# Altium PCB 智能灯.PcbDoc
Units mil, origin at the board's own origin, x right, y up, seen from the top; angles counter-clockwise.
Board outline 3947.04 x 3947.04 mil, 2 copper layers (Top Layer, Bottom Layer); 72 components, 44 nets, 338 pads, 4 vias.
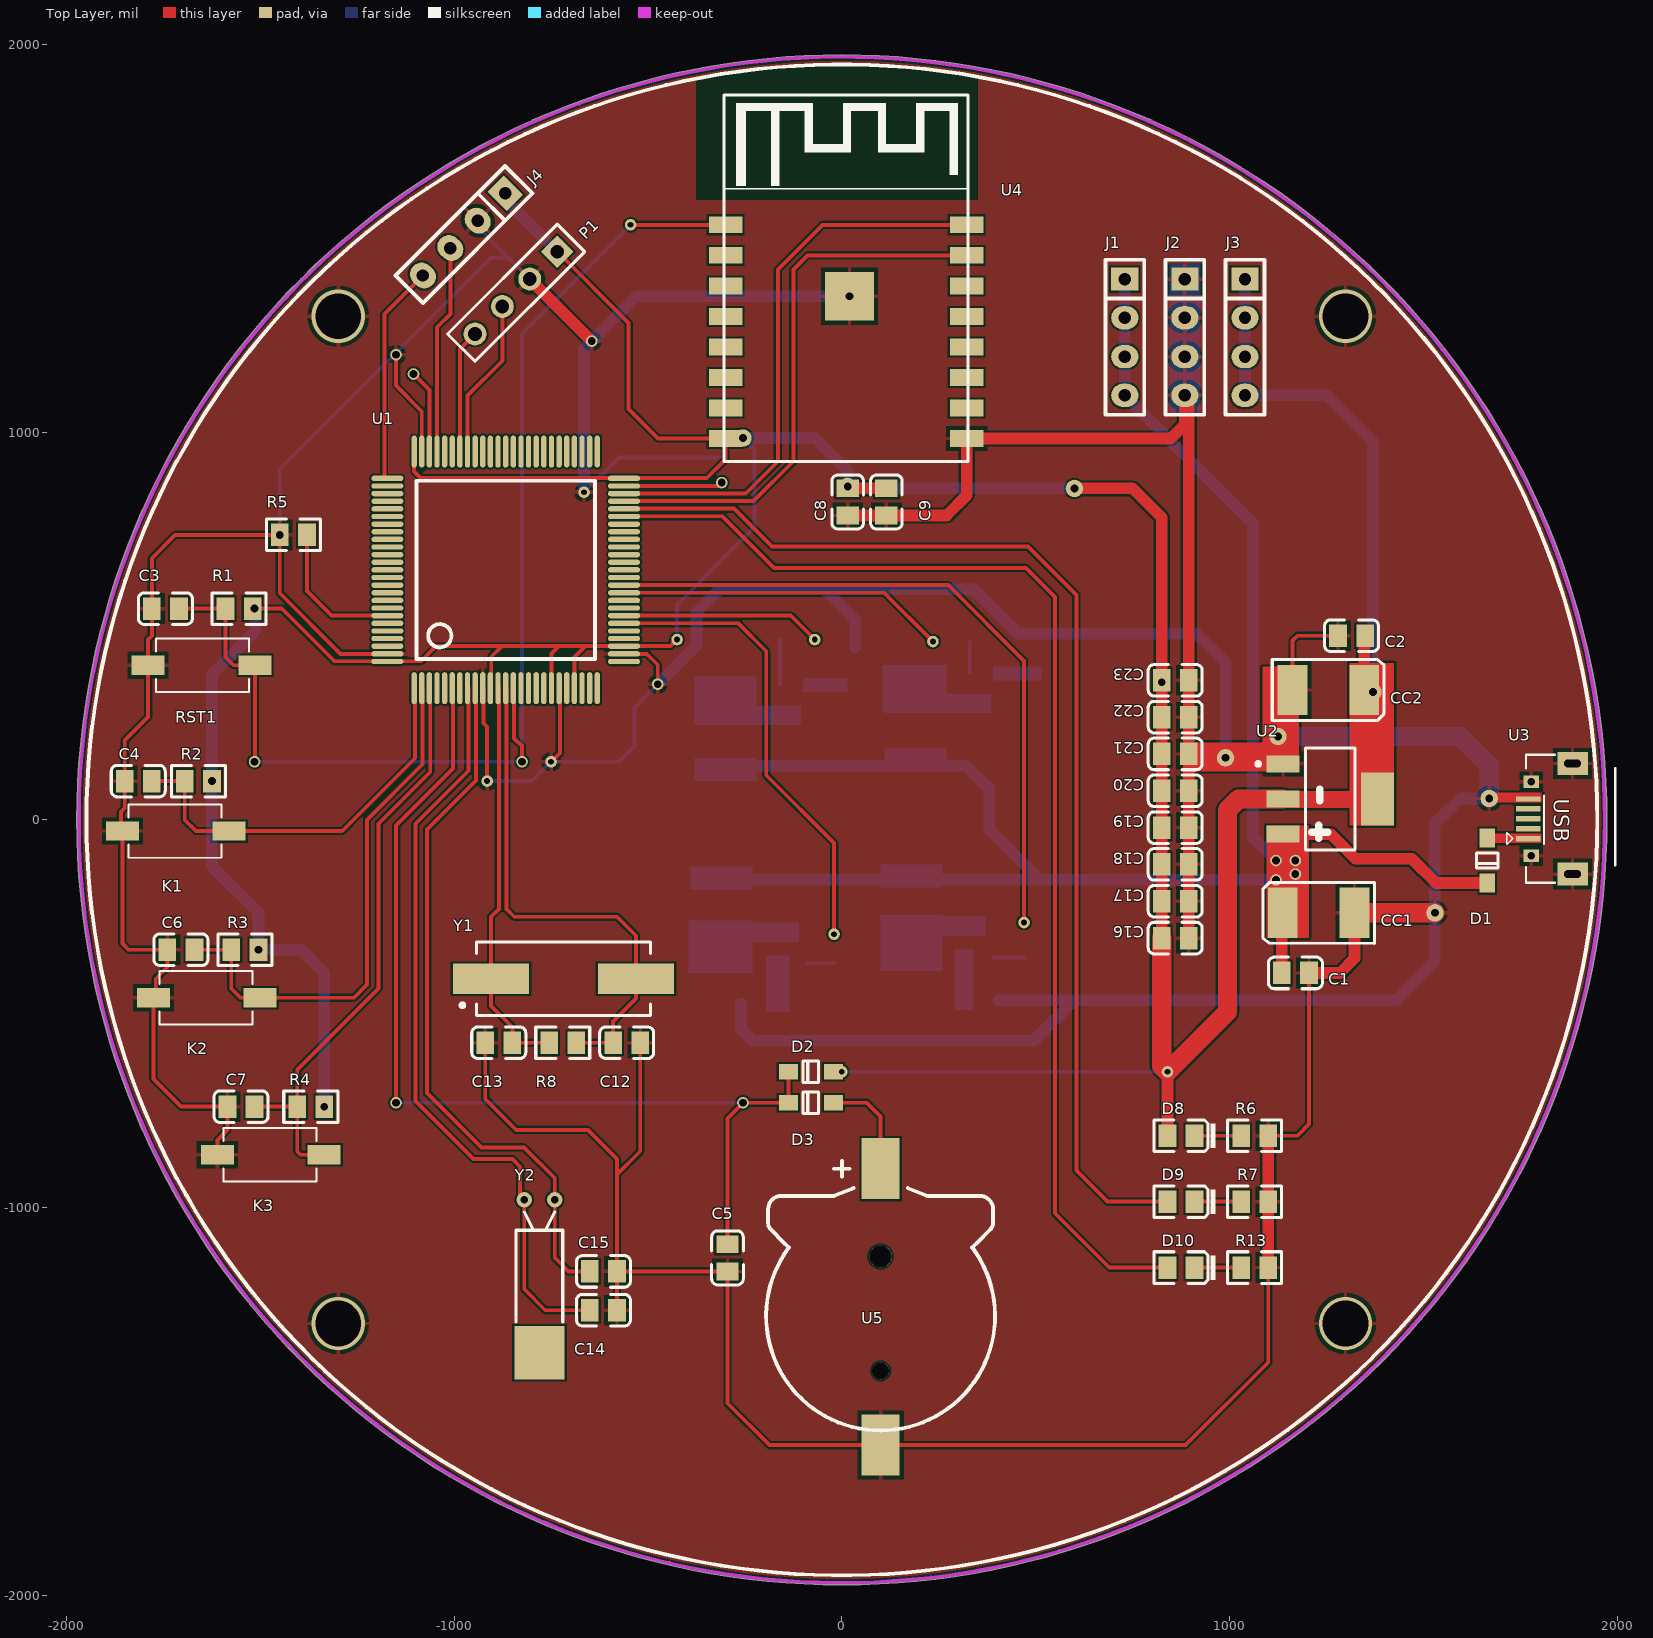
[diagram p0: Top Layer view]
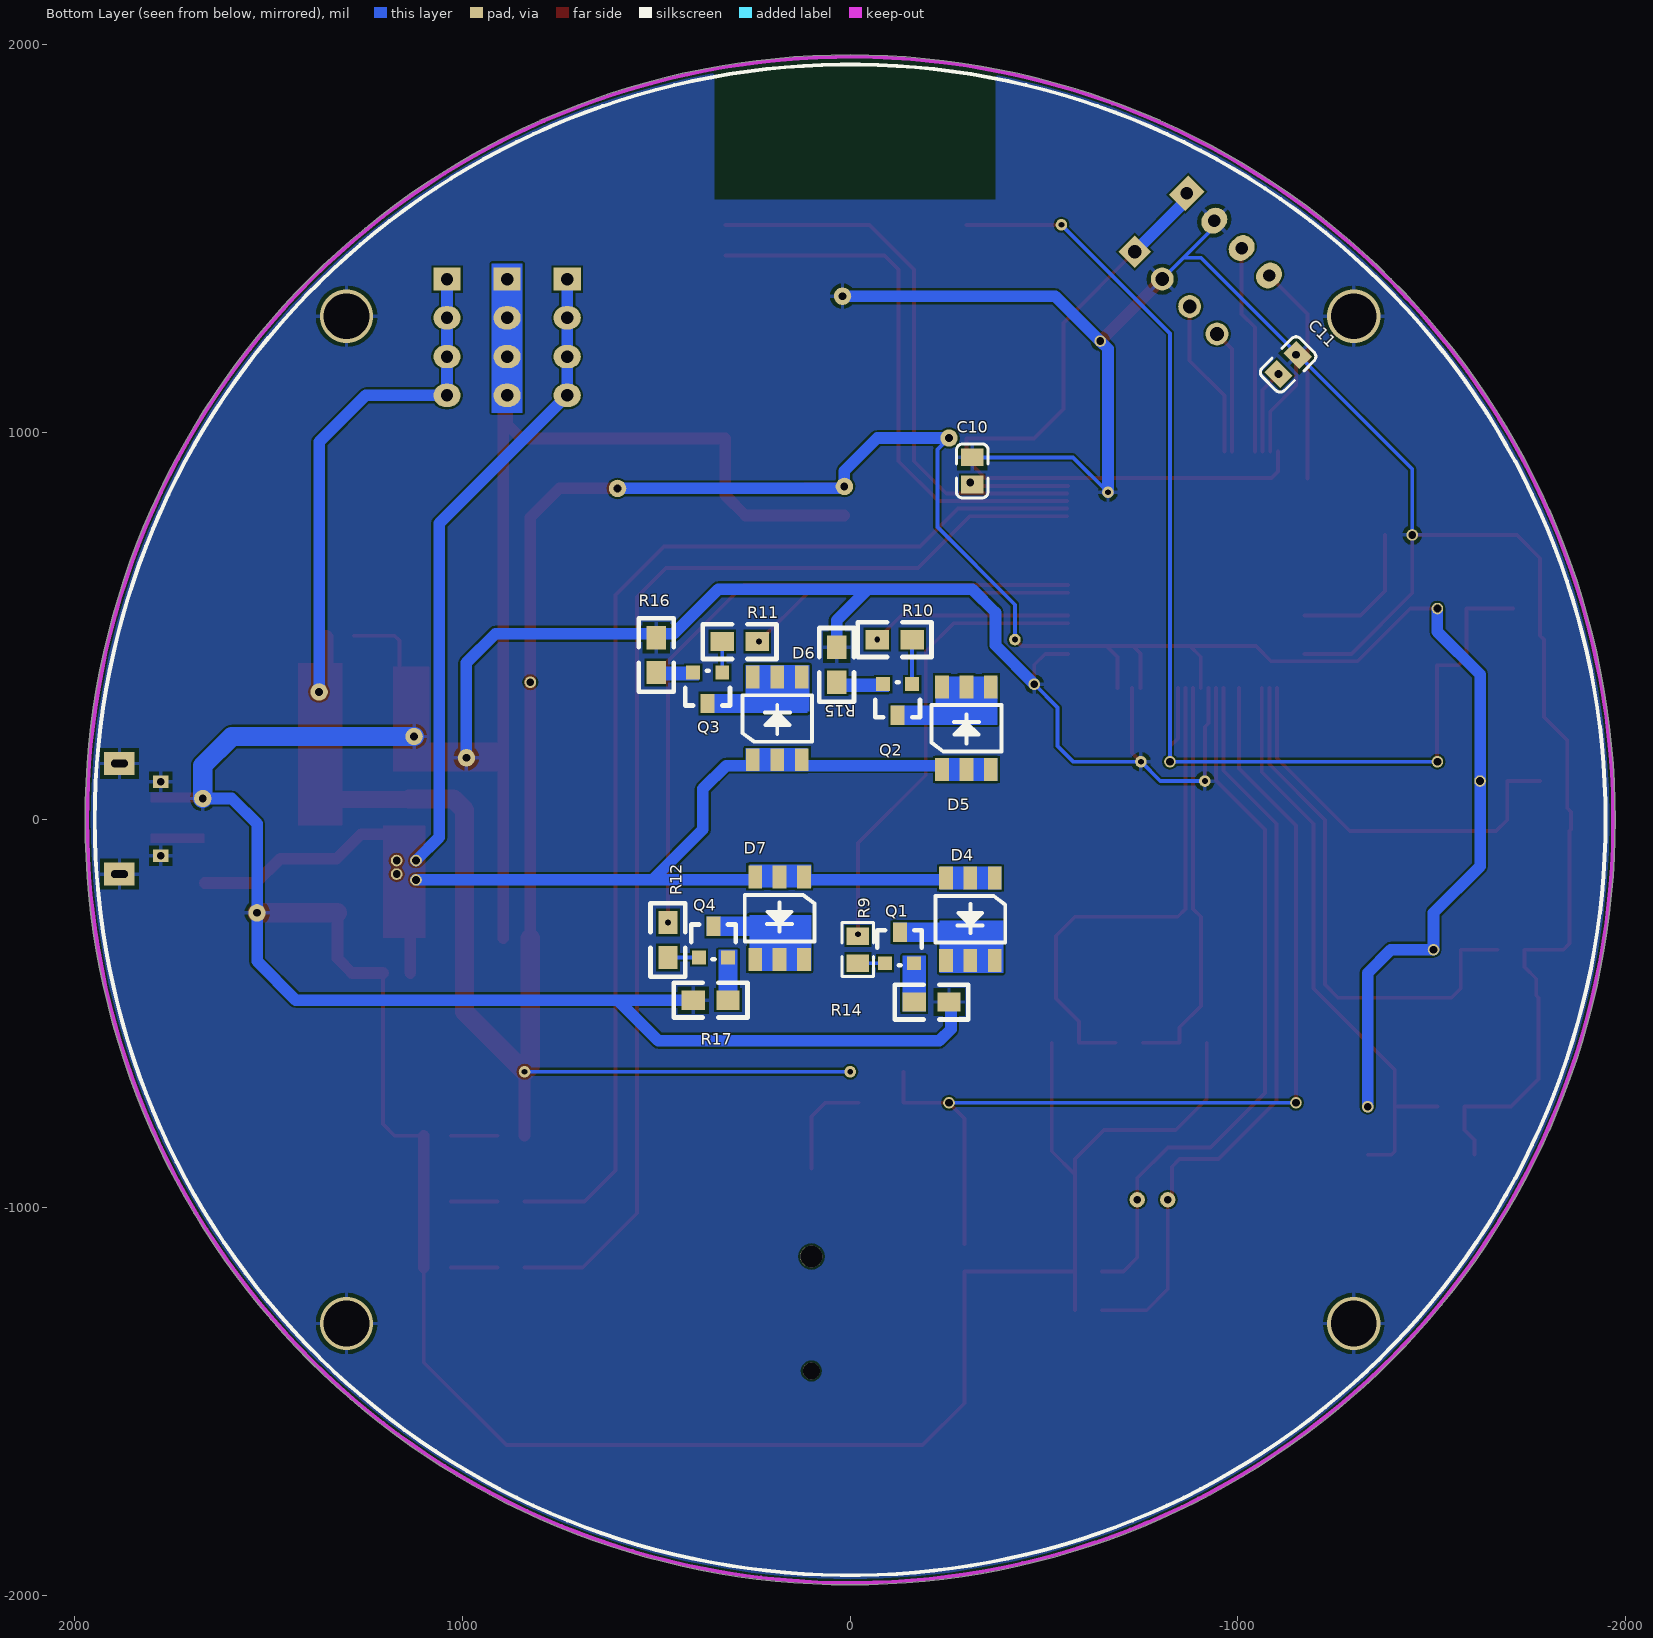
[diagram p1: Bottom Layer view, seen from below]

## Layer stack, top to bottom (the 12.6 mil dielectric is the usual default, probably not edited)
Top Solder: solder mask 0.4, Solder Resist, Dk 3.5
Top Layer: signal copper 1.4
Dielectric 1: dielectric 12.6, FR-4, Dk 4.8
Bottom Layer: signal copper 1.4
Bottom Solder: solder mask 0.4, Solder Resist, Dk 3.5

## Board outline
-1973.52,0 ccw(c0,0) 0,-1973.52 ccw(c0,0) 1973.52,0 ccw(c0,0) 0,1973.52 ccw(c0,0)

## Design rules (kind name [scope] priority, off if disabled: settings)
Clearance [All] p1: gap=5
PolygonConnect [All] p1: connectstyle=Relief reliefconductorwidth=10 reliefentries=4 polygonreliefangle="90 Angle" airgapwidth=10
RoutingVias [All] p1: holewidth=28 width=50 viastyle="Through Hole" minholewidth=28 minwidth=50 maxholewidth=28 maxwidth=50
SolderMaskExpansion [All] p1: expansion=4
Width Width_2 [InNet('VUSB')] p1: maxlimit=50 minlimit=10 preferedwidth=30 minimp=50.000000 maximp=50.000000 favimp=50.000000
Width Width_1 [InNet('VCC3.3')] p2: maxlimit=50 minlimit=10 preferedwidth=10 minimp=50.000000 maximp=50.000000 favimp=50.000000
Width [InNet('GND')] p3: maxlimit=50 minlimit=10 preferedwidth=10 minimp=50.000000 maximp=50.000000 favimp=50.000000
30 further rules are at their usual default settings.

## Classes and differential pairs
component class 智能灯: C1 C2 C3 C4 C5 C6 C7 C8 C9 C10 C11 C12 C13 C14 C15 C16 C17 C18 C19 C20 C21 C22 C23 CC1 CC2 D1 D2 D3 D6 D7 D8 D9 D10 J1 J2 J3 J4 K1 K2 K3 P1 Q1 Q2 Q3 Q4 R1 R2 R3 R4 R5 R6 R7 R8 R9 R13 R14 R15 R16 R17 RST1 U1 U2 U3 U4 U5 Y1 Y2

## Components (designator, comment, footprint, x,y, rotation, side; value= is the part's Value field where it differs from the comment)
C1 "104" LC-0805_C 1170,-395 r180 top
C2 "104" LC-0805_C 1315,475 r0 top
C3 "104" LC-0805_C -1745,545 r0 top
C4 "105" LC-0805_C -1815,100 r180 top
C5 "225" LC-0805_C -295,-1130 r90 top
C6 "105" LC-0805_C -1705,-335 r180 top
C7 "105" LC-0805_C -1549.96,-740 r180 top
C8 "10uF" LC-0805_C 15,820 r90 top
C9 "100nF" LC-0805_C 115,820 r90 top
C10 "225" LC-0805_C -315,900.04 r270 bottom
C11 "225" LC-0805_C -1129.78,1174.78 r315 bottom
C12 "22pF" LC-0805_C -555,-575 r180 top
C13 "22pF" LC-0805_C -885,-575 r180 top
C14 "22pF" LC-0805_C -615,-1265 r180 top
C15 "22pF" LC-0805_C -615,-1165 r0 top
C16 "104" LC-0805_C 860,-305 r180 top
C17 "104" LC-0805_C 860,-210 r180 top
C18 "104" LC-0805_C 860,-115 r180 top
C19 "104" LC-0805_C 860,-20 r180 top
C20 "104" LC-0805_C 860,75 r180 top
C21 "104" LC-0805_C 860,170 r180 top
C22 "104" LC-0805_C 860,265 r180 top
C23 "104" LC-0805_C 860,360 r180 top
CC1 "Cap Tan C" TAN-C-6032 1230,-240 r180 top
CC2 "Cap Tan C" TAN-C-6032 1255,335 r0 top
D1 "SS14" LC-SOD-123 1665,-105 r90 top
D2 "SS14" LC-SOD-123 -80,-650 r0 top
D3 "SS14" LC-SOD-123 -80,-730 r0 top
D4 "LED-5050" LED-5050W -375,-151.5 r270 bottom
D5 "LED-5050" LED-5050W -235,131.5 r90 bottom
D6 "LED-5050" LED-5050W 253,156.5 r90 bottom
D7 "LED-5050" LED-5050W 117,-148.5 r270 bottom
D8 "红灯 0805" LC-0805_LED_S1 875,-815 r180 top
D9 "蓝灯 0603" LC-0805_LED_S1 875,-985 r180 top
D10 "蓝灯 0603" LC-0805_LED_S1 875,-1155 r180 top
J1 "Pin HDR1X4" "Pin HDR1X4/2.54mm-S" 730,1395 r0 top
J2 "Pin HDR1X4" "Pin HDR1X4/2.54mm-S" 885,1395 r0 top
J3 "Pin HDR1X4" "Pin HDR1X4/2.54mm-S" 1040,1395 r0 top
J4 "Pin HDR1X4" "Pin HDR1X4/2.54mm-S" -868.58,1616.42 r315 top
K1 "KEY" KEY_2 -1710,-45 r180 top
K2 "KEY" KEY_2 -1630,-475 r180 top
K3 "KEY" KEY_2 -1465,-880 r180 top
P1 "Header 4" HDR1X4 -734.29,1465.71 r225 top
Q1 "8050" SOT-23 -125,-335 r180 bottom
Q2 "8050" SOT-23 -125,315 r0 bottom
Q3 "8060" SOT-23 365,345 r0 bottom
Q4 "8050" SOT-23 355,-320 r180 bottom
R1 "10KΩ" LC-0805_R -1555,545 r0 top
R2 "10KΩ" LC-0805_R -1660,100 r0 top
R3 "10KΩ" LC-0805_R -1540,-335 r0 top
R4 "10KΩ" LC-0805_R -1370,-740 r0 top
R5 "10KΩ" LC-0805_R -1415,735 r180 top
R6 "47KΩ" LC-0805_R 1065.04,-815 r0 top
R7 "47KΩ" LC-0805_R 1065.04,-985 r0 top
R8 "1MΩ" LC-0805_R -719.96,-575 r0 top
R9 "10KΩ" LC-0805_R -20,-335 r90 bottom
R10 "10KΩ" 0805R -160,465 r0 bottom
R11 "10KΩ" 0805R 330,460 r180 bottom
R12 "10KΩ" 0805R 470,-355 r90 bottom
R13 "47KΩ" LC-0805_R 1065.04,-1155 r0 top
R14 "75Ω" 0805R -165,-470 r180 bottom
R15 "75Ω" 0805R 35,355 r90 bottom
R16 "75Ω" 0805R 500,380 r90 bottom
R17 "75Ω" 0805R 315,-465 r0 bottom
RST1 "RESET" KEY_2 -1660,415 r0 top
U1 "STM32F407VGT6" "LQFP100 14x14" -867.2,644.57 r0 top
U2 "AMS1117" SOT-223 1265,65 r270 top
U3 "USB" USB_B 1845,-122.28 r90 top
U4 "ESP-12S Module" "ESP-12S Module" 11.02,1259.41 r0 top
U5 "BAT" CR1220_A 100,-1280 r90 top
Y1 "8MHz" XTAL-SMD -905,-410 r0 top
Y2 "32.768KHz" OSC-3x8-WI-B -740.63,-980 r180 top

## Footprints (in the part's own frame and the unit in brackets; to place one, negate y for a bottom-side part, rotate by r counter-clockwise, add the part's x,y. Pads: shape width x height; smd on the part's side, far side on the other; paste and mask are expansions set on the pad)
0805R [mil]
  rect 60x50 smd: 1(0,0) 2(90,0)
  silkscreen extent -50,-45 140,45, body extent 1,-25 80,25, height 15
CR1220_A [mm] "纽扣电池座"
  round 1.1 hole 1.1: 0(-3.6,0)
  round 1.45 hole 1.45: 0(3.9,0)
  rect 4x2.5 smd: 1(9.652,0) 2(-8.458,0)
  silkscreen extent -7.5,-7.5 10.16,7.5, body extent -9.42,-7.45 10.34,7.45, height 4.05
"ESP-12S Module" [mm]
  rect 2.2x1.1 smd: 1(-7.9,7) 2(-7.9,5) 3(-7.9,3) 4(-7.9,1) 5(-7.9,-1) 6(-7.9,-3) 7(-7.9,-5) 8(-7.9,-7) 9(7.9,-7) 10(7.9,-5) 11(7.9,-3) 12(7.9,-1) 13(7.9,1) 14(7.9,3) 15(7.9,5) 16(7.9,7)
  rect 3.2x3.2 smd: 17(0.22,2.321)
  silkscreen extent -8,-8.5 8,15.5
HDR1X4 [mm] "Connector; Header; 4 Position"
  rect 1.5x1.5 hole 0.9: 1(0,0)
  round 1.5 hole 0.9: 2(2.54,0) 3(5.08,0) 4(7.62,0)
  silkscreen extent -1.27,-1.27 8.89,1.27, body extent -1.27,-1.27 8.89,1.27, height 7.58
KEY_2 [mil] "贴片"
  rect 85x49.37 smd: 1(-129.57,-16.14) 2(146.02,-16.14)
  silkscreen extent -110,-85 130,53, body extent -110,-88 130,58
LC-0805_C [mm]
  rect 1.16x1.47 smd: 1(-0.89,0) 2(0.89,0)
  silkscreen extent -1.77,-1.04 1.77,1.04, body extent -1,-0.62 1,0.63, height 0.77
LC-0805_LED_S1 [mm]
  rect 1.16x1.47 smd: A(0.89,0) K(-0.89,0)
  silkscreen extent -2.25,-1.04 1.77,1.03, body extent -1.01,-0.62 1.01,0.62, height 1.1
LC-0805_R [mm]
  rect 1.16x1.47 smd: 1(-0.89,0) 2(0.89,0)
  silkscreen extent -1.77,-1.04 1.77,1.03, body extent -1,-0.62 1,0.63, height 0.49
LC-SOD-123 [mm]
  rect 1.25x1 smd: 1(1.475,0) 2(-1.475,0)
  silkscreen extent -0.5,-0.7 0.5,0.7, body extent -1.85,-0.77 1.85,0.78, height 1.35
LED-5050W [mil]
  rect 59.06x35.43 smd: 1(-1.5,-2) 2(211.5,-2) 3(-1.5,-65) 4(211.5,-65) 5(-1.5,-128) 6(211.5,-128)
  silkscreen extent 45,-155 165,25, body extent -1,-162 211,35, height 65
"LQFP100 14x14" [mm]
  oval 0.35x2.1 smd: 1(-6,-7.747) 2(-5.5,-7.747) 3(-5,-7.747) 4(-4.5,-7.747) 5(-4,-7.747) 6(-3.5,-7.747) 7(-3,-7.747) 8(-2.5,-7.747) 9(-2,-7.747) 10(-1.5,-7.747) 11(-1,-7.747) 12(-0.5,-7.747) 13(0,-7.747) 14(0.5,-7.747) 15(1,-7.747) 16(1.5,-7.747) 17(2,-7.747) 18(2.5,-7.747) 19(3,-7.747) 20(3.5,-7.747) 21(4,-7.747) 22(4.5,-7.747) 23(5,-7.747) 24(5.5,-7.747) 25(6,-7.747) 51(6,7.758) 52(5.5,7.758) 53(5,7.758) 54(4.5,7.758) 55(4,7.758) 56(3.5,7.758) 57(3,7.758) 58(2.5,7.758) 59(2,7.758) 60(1.5,7.758) 61(1,7.758) 62(0.5,7.758) 63(0,7.758) 64(-0.5,7.758) 65(-1,7.758) 66(-1.5,7.758) 67(-2,7.758) 68(-2.5,7.758) 69(-3,7.758) 70(-3.5,7.758) 71(-4,7.758) 72(-4.5,7.758) 73(-5,7.758) 74(-5.5,7.758) 75(-6,7.758)
  oval 2.1x0.35 smd: 26(7.752,-5.994) 27(7.752,-5.494) 28(7.752,-4.994) 29(7.752,-4.494) 30(7.752,-3.994) 31(7.752,-3.494) 32(7.752,-2.994) 33(7.752,-2.494) 34(7.752,-1.994) 35(7.752,-1.494) 36(7.752,-0.994) 37(7.752,-0.494) 38(7.752,0.006) 39(7.752,0.506) 40(7.752,1.006) 41(7.752,1.506) 42(7.752,2.006) 43(7.752,2.506) 44(7.752,3.006) 45(7.752,3.506) 46(7.752,4.006) 47(7.752,4.506) 48(7.752,5.006) 49(7.752,5.506) 50(7.752,6.006) 76(-7.752,6.006) 77(-7.752,5.506) 78(-7.752,5.006) 79(-7.752,4.506) 80(-7.752,4.006) 81(-7.752,3.506) 82(-7.752,3.006) 83(-7.752,2.506) 84(-7.752,2.006) 85(-7.752,1.506) 86(-7.752,1.006) 87(-7.752,0.506) 88(-7.752,0.006) 89(-7.752,-0.494) 90(-7.752,-0.994) 91(-7.752,-1.494) 92(-7.752,-1.994) 93(-7.752,-2.494) 94(-7.752,-2.994) 95(-7.752,-3.494) 96(-7.752,-3.994) 97(-7.752,-4.494) 98(-7.752,-4.994) 99(-7.752,-5.494) 100(-7.752,-5.994)
  silkscreen extent -5.84,-5.84 5.84,5.85, body extent -8,-7.98 8,8.03, height 1.45
OSC-3x8-WI-B [mm]
  rect 3.3x3.5 smd: 0(1,10.033)
  round 1 hole 0.5: 1(0,0) 2(2,0)
  silkscreen extent -0.52,0.8 2.52,8, body extent -0.48,-0.13 2.52,10.05, height 3.03
"Pin HDR1X4/2.54mm-S" [mil]
  rect 70x60 hole 32: 1(0,0)
  oval 70x60 hole 32: 2(0,-100) 3(0,-200) 4(0,-300)
  silkscreen extent -50,-350 50,50, body extent -50,-350 50,50, height 336
SOT-23 [mil]
  rect 36x36 smd: B(-35,-35) E(40,-35)
  rect 36x50 smd: C(3,45)
  silkscreen extent -55,-40 60,50, body extent -54,-48 60,62, height 47
SOT-223 [mm] "ASM1117系列"
  rect 1.1x2.15 smd: 1(-2.012,-3.227) 2(0.288,-3.227) 3(2.588,-3.227)
  rect 3.5x2.15 smd: 2(0.288,2.973)
  silkscreen extent -3.06,-4.98 3.64,1.5, body extent -3,-3.48 3.5,3.48, height 1.7
TAN-C-6032 [mm]
  rect 1.95x3.3 smd: 1(-2.35,0) 2(2.35,0)
  silkscreen extent -3.68,-2.01 3.66,2, body extent -3,-1.6 3,1.6, height 2.6
USB_B [mm]
  rect 0.35x1.6 smd: 1(1.875,1.884) 2(2.525,1.884) 3(3.175,1.884) 4(3.825,1.884) 5(4.475,1.884)
  rect 1.5x2 hole 0.5 slot 1.1 at 90 deg: 5(-0.45,-1.016) 5(6.8,-1.016)
  rect 0.8x1 hole 0.5: 5(0.75,1.694) 5(5.6,1.694)
  silkscreen extent -1.02,-3.81 7.37,3.28, body extent -0.83,-3.73 7.18,1.87, height 2.8
XTAL-SMD [mm]
  rect 5x2 smd: 1(0,0) 2(9.5,0)
  silkscreen extent -2,-2.4 10.45,2.4, body extent -1.95,-2.46 11.45,2.44, height 4

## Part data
C1 C2 C4 C5 C6 C7 C8 C9 C10 C11 C16 C17 C18 C19 C20 C21 C22 C23: library part "0805 6.8nF (682) 10% 50V", "贴片电容"
C3: library part "0805 330nF (334) 10% 50V", "贴片电容"
C12 C13 C14 C15: library part "0805 6pF (6R0) 0.25pF 50V", "贴片电容"
CC1 CC2: "Polarized Capacitor (Radial)"
D1 D2 D3: library part D
D8: library part "0805 红灯", "发光二极管"
D9 D10: library part "0603 蓝灯", "发光二极管"
K1 K2 K3: "微动开关"
P1: "Header, 4-Pin"
Q1 Q2 Q3 Q4: library part NPN, "NPN三极管"
R1 R8: library part "0805 390KΩ (3903) 1%", "贴片电阻"
R2 R3 R4 R6 R7 R9 R10 R11 R12 R13: library part "0805 11KΩ (1102) 1%", "贴片电阻"
R5: library part "0805 1.8KΩ (1801) 1%", "贴片电阻"
R14 R15 R16 R17: library part "0805 1.2KΩ (1201) 1%", "贴片电阻"
RST1: library part KEY, "微动开关"
U2: "3.3V电压转换器AMS1117"
U5: "纽扣电池座CR1220"
Y1 Y2: library part XTAL, "晶体振荡器"

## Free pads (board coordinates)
  round 30 hole 20: 2(-1625,100) 2(-1515,150) 2(-1515,545) 2(-1505,-335) 2(-1450,735) 2(-1334.96,-740) 2(-1150,-730) 2(-1150,1200) 2(-1105,1150) 2(-825,150) 2(-645,1235) 2(-475,350) 2(-310,870) 2(-255,-730) 2(825,355) 2(1120,-155) 2(1120,-105) 2(1170,-140) 2(1170,-105)
  round 30 hole 15: 2(-915,100) 2(-750,150) 2(-665,845) 2(-545,1535) 2(-425,465) 2(-70,465) 2(-20,-295) 2(0,-650) 2(235,460) 2(470,-265) 2(840,-650)
  round 45 hole 20: 2(-255,985) 2(15,860) 2(19.69,1350.8) 2(600,855) 2(990,160) 2(1125,215) 2(1370,330) 2(1530,-240) 2(1670,55)

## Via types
v1: diameter 137.8, hole 118.11, Top Layer to Bottom Layer, 4 vias

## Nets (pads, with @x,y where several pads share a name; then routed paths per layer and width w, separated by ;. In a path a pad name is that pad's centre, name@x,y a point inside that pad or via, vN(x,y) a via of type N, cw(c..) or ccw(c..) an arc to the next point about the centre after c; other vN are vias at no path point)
DS1: pad.2@-20,-295 R9.2 U1.31 | length 1199.3
  Top Layer w10: U1.31 -266.99,506.99 -195,435 -195,115 -20,-60 pad.2@-20,-295
DS2: pad.2@-70,465 R10.2 U1.32 | length 517.5
  Top Layer w10: U1.32 -131.68,526.68 pad.2@-70,465
DS3: pad.2@235,460 R11.2 U1.35 | length 849.1
  Top Layer w10: U1.35 109.27,585.73 pad.2@235,460
DS4: pad.2@470,-265 R12.2 U1.36 | length 1787.9
  Top Layer w10: U1.36 274.58,605.42 470,410 pad.2@470,-265
GND: C1.1 C2.1 C3.1 C4.2 C5.1 C6.2 C7.2 C8.1 C9.1 C10.1 C11.1 C12.1 C13.2 C14.1 C15.2 C16.1 C17.1 C18.1 C19.1 C20.1 C21.1 C22.1 C23.1 CC1.1 CC2.1 J2.1 J2.2 J2.3 J2.4 J4.2 K1.2 K2.2 K3.2 P1.2 pad.2@19.69,1350.8 pad.2@990,160 pad.2@1125,215 pad.2@1530,-240 pad.2@1670,55 pad.2@-475,350 pad.2@-645,1235 pad.2@-665,845 pad.2@-750,150 pad.2@-915,100 pad.2@-1150,1200 pad.2@-1450,735 R5.2 R6.2 R7.2 R13.2 R14.2 R15.2 R16.2 R17.2 RST1.1 U1.10 U1.20 U1.27 U1.74 U1.99 U2.1 U3.5 U4.9 U4.17 U5.2 | length 20334.2
  Top Layer w10: K3.2 -1611.02,-826.02 -1585,-800 C7.2 -1705,-740 -1776.02,-668.98 K2.2 -1770,-452.83 -1770,-410 -1740.04,-380.04 C6.2 -1840,-335 -1856.02,-318.98 K1.2 -1860,-24.88 -1860,20 -1850.04,29.96 C4.2 -1850.04,204.96 -1789.57,265.43 RST1.1 -1789.57,465.43 -1780.04,474.96 C3.1 -1780.04,674.96 -1720,735 R5.2 ; R5.2 -1450,585 -1293.25,428.25 U1.99 ; pad.2@-1150,1200 -1150,1120 -1083.74,1053.74 U1.74 ; U1.10@-924.06,340.01 -924.06,249.06 -915,240 pad.2@-915,100 ; C13.2 -920.04,-719.96 -840,-800 -655,-800 -579.96,-875.04 -579.96,-914.96 ; pad.2@-750,150 -727.2,172.8 U1.20@-727.2,340.01 ; C14.1 C15.2 ; U1.27 -503.25,428.25 -475,400 pad.2@-475,350 ; C12.1 -519.96,-854.96 -579.96,-914.96 ; R13.2 1100.08,-1399.92 887,-1613 U5.2 -187,-1613 -295,-1505 C5.1 C5.1 C15.2 ; R6.2 1175,-815 1205.04,-784.96 C1.1 ; CC2.1 1162.48,462.48 1175,475 C2.1 ; C15.2 -579.96,-914.96
  Top Layer w30: P1.2 pad.2@-645,1235 ; C8.1 C9.1 269.96,784.96 322.05,837.05 U4.9 848.82,983.82 885,1020 J2.4 895.04,1084.96 C23.1 C22.1 C21.1 C20.1 C19.1 C18.1 C17.1 C16.1 ; R13.2 R7.2 R6.2 ; C1.1 1285,-395 1322.52,-357.48 CC1.1
  Top Layer w50: CC1.1 pad.2@1530,-240
  Bottom Layer w10: pad.2@-1450.04,735 -1450.04,904.96 -905,1450 -860,1450 ; J4.2 -939.29,1529.29 -860,1450 ; pad.2@-915,100 -800,100 -750,150 -575,150 -535,190 -535,290 pad.2@-475,350 ; P1.2 -860,1450 ; pad.2@-665,845 -574.92,935.08 C10.1
  Bottom Layer w30: pad.2@-665,845 -665,1215 -645,1235 -529.2,1350.8 pad.2@19.69,1350.8 ; pad.2@-475,350 -375,450 -375,535 -315,595 -45,595 ; R14.2@-260,-475 -260,-540 -230,-570 495,-570 600,-465 ; R15.2 35,515 -45,595 ; R17.2 600,-465 ; pad.2@990,160 990,405 915,480 455,480 340,595 -45,595 ; pad.2@1670,55 1595,55 1530,-10 1530,-240 1530,-365 1430,-465 600,-465
  Bottom Layer w50: pad.2@1125,215 1595,215 1670,140 pad.2@1670,55
  other v1: -1299.21,-1299.21 1299.21,-1299.21 -1299.21,1299.21 1299.21,1299.21
KEY1: C4.1 K1.1 R2.1 U1.1 | length 1049.6
  Top Layer w10: C4.1 R2.1 -1695.04,0.04 -1666.14,-28.86 K1.1 -1288.86,-28.86 -1101.22,158.78 U1.1@-1101.22,340.01
KEY2: C6.1 K2.1 R3.1 U1.2 | length 1393.3
  Top Layer w10: C6.1 R3.1 -1575.04,-434.96 -1551.14,-458.86 K2.1 -1258.86,-458.86 -1225,-425 -1225,0 -1081.54,143.46 U1.2@-1081.54,340.01
KEY3: C7.1 K3.1 R4.1 U1.3 | length 1520.3
  Top Layer w10: C7.1 R4.1 ; K3.1 -1396.14,-863.86 -1405.04,-854.96 R4.1 ; U1.3@-1061.85,340.01 -1061.85,123.15 -1195,-10 -1195,-435 -1405.04,-645.04 R4.1
LED1: D9.A U1.46 | length 3010.1
  Top Layer w10: U1.46@-559.79,802.7 -277.7,802.7 -180,705 480,705 605,580 605,-905 685,-985 D9.A
LED2: D10.A U1.45 | length 3133.9
  Top Layer w10: U1.45@-559.79,783.02 -308.02,783.02 -175,650 475,650 550,575 550,-1015 690,-1155 D10.A
NetC10_2: C10.2 pad.2@-310,870 U1.49 | length 255.6
  Top Layer w10: U1.49 -318.68,861.32 pad.2@-310,870
NetC11_2: C11.2 pad.2@-1105,1150 U1.73 | length 217
  Top Layer w10: pad.2@-1105,1150 -1064.06,1109.06 U1.73
NetD1_1: D1.1 U3.1
NetD3_1: D3.1 U5.1 | length 271.4
  Top Layer w10: D3.1 65,-730 100,-765 U5.1
NetD4_2: D4.2 D4.4 D4.6 Q1.C
NetD5_2: D5.2 D5.4 D5.6 Q2.C
NetD6_2: D6.2 D6.4 D6.6 Q3.C
NetD7_2: D7.2 D7.4 D7.6 Q4.C
NetD8_K: D8.K R6.1 | length 120
  Top Layer w10: D8.K R6.1
NetD9_K: D9.K R7.1 | length 120
  Top Layer w10: D9.K R7.1
NetD10_K: D10.K R13.1 | length 120
  Top Layer w10: D10.K R13.1
NetQ1_B: Q1.B R9.1 | length 70
  Bottom Layer w10: Q1.B Q1.B R9.1
NetQ1_E: Q1.E R14.1
NetQ2_B: Q2.B R10.1 | length 115
  Bottom Layer w10: Q2.B R10.1
NetQ2_E: Q2.E R15.1
NetQ3_B: Q3.B R11.1 | length 80
  Bottom Layer w10: Q3.B R11.1
NetQ3_E: Q3.E R16.1
NetQ4_B: Q4.B R12.1 | length 80
  Bottom Layer w10: Q4.B R12.1
NetQ4_E: Q4.E R17.1
NetR5_1: R5.1 U1.94 | length 378.8
  Top Layer w10: R5.1 -1379.96,589.96 -1316.68,526.68 U1.94
NRST: C3.2 pad.2@-545,1535 pad.2@-825,150 pad.2@-1515,150 R1.1 RST1.2 U1.14 U4.1 | length 3213.4
  Top Layer w10: C3.2 R1.1 -1590.04,420.04 -1568.86,398.86 RST1.2 -1513.98,151.02 pad.2@-1515,150 ; U1.14@-845.31,340.01 -845.31,210.31 -825,190 pad.2@-825,150 ; pad.2@-545,1535 U4.1
  Bottom Layer w10: pad.2@-1515,150 -825,150 -825,1255 pad.2@-545,1535
OSC32_IN: C14.2 U1.8 Y2.2 | length 1973.9
  Top Layer w10: U1.8@-963.43,340.01 -963.43,126.57 -1100,-10 -1100,-725 -950,-875 -850,-875 -830,-895 -830,-969.37 Y2.2 -819.37,-1210.63 -765,-1265 C14.2
OSC32_OUT: C15.1 U1.9 Y2.1 | length 1828.2
  Top Layer w10: U1.9@-943.74,340.01 -943.74,101.89 -943.43,101.57 -1070,-25 -1070,-705 -930,-845 -820,-845 -740.63,-924.37 Y2.1 -740.63,-1129.37 -705,-1165 C15.1
OSC_IN: C13.1 R8.1 U1.12 Y1.1 | length 1041.2
  Top Layer w10: U1.12@-884.69,340.01 -884.69,-229.69 -905,-250 Y1.1 -905,-480 -849.96,-535.04 C13.1 R8.1
OSC_OUT: C12.2 R8.2 U1.13 Y1.2 | length 1327.9
  Top Layer w10: U1.13@-865,340.01 -865,-230 -845,-250 -580,-250 -530.99,-299.01 Y1.2 -530.99,-460.99 -590.04,-520.04 C12.2 R8.2
SWCLK: J4.4 U1.76 | length 564.4
  Top Layer w10: U1.76@-1180,881.01 -1180,1305 J4.4
SWDIO: J4.3 U1.72 | length 539.2
  Top Layer w10: U1.72 -1044.37,1270.63 -1010,1305 J4.3
U1_RX: P1.4 U1.69 | length 319.7
  Top Layer w10: U1.69 -985.31,1214.69 P1.4
U1_TX: P1.3 U1.68 | length 411.5
  Top Layer w10: U1.68 -965.63,1094.37 -875.71,1184.29 P1.3
U3_RX: U1.48 U4.16 | length 1458.8
  Top Layer w10: U1.48@-559.79,842.07 -247.93,842.07 -165,925 -165,1420 -50,1535 U4.16
U3_TX: U1.47 U4.15 | length 1434.4
  Top Layer w10: U1.47@-559.79,822.39 -227.61,822.39 -125,925 -125,1420 -88.74,1456.26 U4.15
VBAT: C5.2 D2.2 D3.2 pad.2@-255,-730 pad.2@-1150,-730 U1.6 | length 2589.4
  Top Layer w10: pad.2@-1150,-730 -1150,-15 -1002.8,132.2 U1.6@-1002.8,340.01 ; C5.2 -295,-770 -255,-730 D3.2 D2.2
  Bottom Layer w10: -1135,-730 pad.2@-255,-730
VCC3.3: C2.2 C8.2 C9.2 C16.2 C17.2 C18.2 C19.2 C20.2 C21.2 C22.2 C23.2 CC2.2 D2.1 D8.A J3.1 J3.2 J3.3 J3.4 J4.1 P1.1 pad.2@0,-650 pad.2@15,860 pad.2@600,855 pad.2@825,355 pad.2@840,-650 pad.2@1370,330 pad.2@-255,985 pad.2@-425,465 pad.2@-1334.96,-740 pad.2@-1505,-335 pad.2@-1515,545 pad.2@-1625,100 R1.2 R2.2 R3.2 R4.2 U1.11 U1.19 U1.22 U1.28 U1.50 U1.75 U1.100 U2.2 U4.8 | length 11657.3
  Top Layer w10: R1.2 -1445,545 -1309,409 -1086,409 -1046.63,448.37 -876.63,448.37 ; U1.75 -1103.43,898.43 -1086.44,881.44 -348.56,881.44 -300,930 U4.8 -473.82,983.82 -550,1060 -550,1281.42 P1.1 ; U1.11@-904.37,340.01 -904.37,420.63 -876.63,448.37 ; U1.19 -749.09,429.28 -730,448.37 ; U1.22 -690.04,419.96 -661.63,448.37 ; pad.2@-425,465 -441.63,448.37 -661.63,448.37 ; -876.63,448.37 -730,448.37 ; -730,448.37 -661.63,448.37
  Top Layer w30: C8.2 C9.2 ; pad.2@600,855 750,855 824.96,780.04 C23.2 C22.2 C21.2 C20.2 C19.2 C18.2 C17.2 C16.2 ; D8.A 839.96,-650.04 pad.2@840,-650 ; CC2.2 1347.52,472.48 C2.2
  Top Layer w50: C16.2 824.96,-635.04 pad.2@839.96,-650.04 ; pad.2@840,-650 995,-495 995,25 1023.66,53.66 U2.2@1137.95,53.66
  Bottom Layer w10: pad.2@-425,465 -425,555 -225,755 -225,955 pad.2@-255,985 ; pad.2@0,-650 pad.2@840,-650
  Bottom Layer w30: pad.2@-1515,545 -1515,485 -1625,375 -1625,100 -1625,-120 -1505,-240 -1505,-335 -1395,-335 -1334.96,-395.04 pad.2@-1334.96,-740 ; J4.1 -868.58,1600 P1.1 ; pad.2@-255,985 -70,985 15,900 15,860 20,855 pad.2@600,855 ; J3.1 J3.2 J3.3 J3.4 1250,1095 1370,975 pad.2@1370,330
VUSB: C1.2 CC1.2 D1.2 D4.1 D4.3 D4.5 D5.1 D5.3 D5.5 D6.1 D6.3 D6.5 D7.1 D7.3 D7.5 J1.1 J1.2 J1.3 J1.4 pad.2@1120,-105 pad.2@1120,-155 pad.2@1170,-105 pad.2@1170,-140 U2.3 | length 5131.8
  Top Layer w30: C1.2 1134.96,-242.52 CC1.2 1137.48,-37.36 U2.3 1261.89,-36.89 1325,-100 1470,-100 1533.07,-163.07 D1.2
  Bottom Layer w30: D4.1@-365,-155 119,-155 pad.2@1120,-155 ; D5.5@-360,140 125,140 251,140 320,140 380,80 380,-25 505,-150 ; J1.1 J1.2 J1.3 J1.4 1060,765 1060,-45 pad.2@1120,-105
pads on no net: U1.4 U1.5 U1.7 U1.15 U1.16 U1.17 U1.18 U1.21 U1.23 U1.24 U1.25 U1.26 U1.29 U1.30 U1.33 U1.34 U1.37 U1.38 U1.39 U1.40 U1.41 U1.42 U1.43 U1.44 U1.51 U1.52 U1.53 U1.54 U1.55 U1.56 U1.57 U1.58 U1.59 U1.60 U1.61 U1.62 U1.63 U1.64 U1.65 U1.66 U1.67 U1.70 U1.71 U1.77 U1.78 U1.79 U1.80 U1.81 U1.82 U1.83 U1.84 U1.85 U1.86 U1.87 U1.88 U1.89 U1.90 U1.91 U1.92 U1.93 U1.95 U1.96 U1.97 U1.98 U3.2 U3.3 U3.4 U4.2 U4.3 U4.4 U4.5 U4.6 U4.7 U4.10 U4.11 U4.12 U4.13 U4.14 U5.0 Y2.0

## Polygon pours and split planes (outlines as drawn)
GND on Top Layer "GND_L01_P012" (solid, remove dead copper, pour order 12): -1968.5,0 ccw(c0,0) 0,-1968.5 ccw(c0,0) 1968.5,0 ccw(c0,0) 0,1968.5 ccw(c0,0)
GND on Bottom Layer "GND_L02_P014" (solid, remove dead copper, pour order 14): -1968.5,0 ccw(c0,0) 0,-1968.5 ccw(c0,0) 1968.5,0 ccw(c0,0) 0,1968.5 ccw(c0,0)

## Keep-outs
Keep-Out Layer:
  circle w10: c0,0 r1968.5

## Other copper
Top Layer:
  rectangle net GND: 880,125 1180,200
  rectangle net GND: 1660,45 1805,70
  rectangle net GND: 1085,125 1180,395
  rectangle net VCC3.3: 1310,-15 1425,405
  rectangle net VCC3.3: 1095,30 1425,75
  rectangle net VUSB: 1095,-305 1205,-15
  rectangle net NetD1_1: 1665,-60 1805,-35
  pour cut-out: -375,1910 -375,1600 350,1600 350,1915 295,1925 40,1950 -209.74,1938.49 -230,1935
Bottom Layer:
  rectangle net NetQ2_E: -100,330 15,365
  rectangle net NetQ3_E: 390,360 515,395
  rectangle net NetD6_2: 110,275 385,325
  rectangle net VUSB: -380,100 -220,160
  rectangle net NetD5_2: -380,245 -105,295
  rectangle net NetD5_2: -380,250 -220,370
  rectangle net NetQ4_E: 290,-490 340,-335
  rectangle net NetD7_2: 140,-300 370,-250
  rectangle net NetQ1_E: -195,-495 -135,-350
  rectangle net NetD4_2: -310,-315 -110,-265
  rectangle net NetD4_2: -395,-395 -230,-260
  rectangle net VUSB: -390,-180 -230,-120
  rectangle net VUSB: 100,-175 260,-115
  rectangle net NetD7_2: 100,-390 260,-245
  rectangle net NetD6_2: 105,280 270,400
  rectangle net VUSB: 110,125 270,185
  rectangle net GND: 845,1050 925,1435
  pour cut-out: -375,1930 -375,1600 350,1600 350,1940 279.79,1948.52 234.93,1954.43 30,1968.5 -179.59,1962.57 -195,1960

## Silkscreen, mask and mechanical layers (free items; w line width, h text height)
Top Overlay:
  circle w10: c0,0 r1948.82
Bottom Overlay:
  circle w10: c0,0 r1948.82
Mechanical 1:
  the board outline again, w47.24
